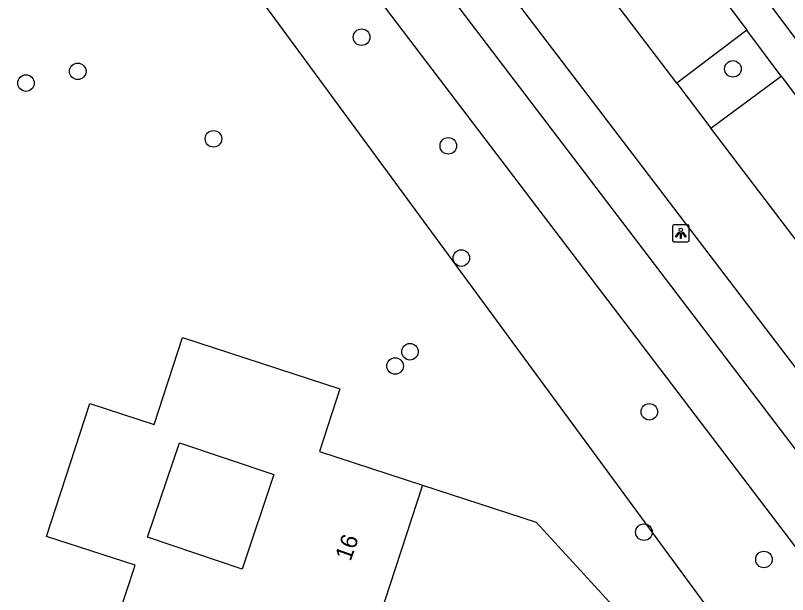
# Model space of a CAD drawing. Extents: x 156664 to 157568, y 383571 to 384421.
# Drawn here: x 156849.91 to 156895.54, y 384208.09 to 384242.31 of the extents above; entities that cross this region are included whole.
import ezdxf

# ---------------------------------------------------------------- set-up
doc = ezdxf.new("R2010")
doc.units = 0
for name, color, linetype in [('IMGEO_Boom', 7, 'Continuous'), ('IMGEO_Fietspad_gesloten', 7, 'Continuous'), ('IMGEO_Groenvoorziening', 7, 'Continuous'), ('IMGEO_Lichtpunt', 7, 'Continuous'), ('IMGEO_Pand', 7, 'Continuous'), ('IMGEO_Pand_nummerreeks', 7, 'Continuous'), ('IMGEO_Parkeervlak_open', 7, 'Continuous'), ('IMGEO_Rijbaan_lokaal_gesloten', 7, 'Continuous'), ('IMGEO_Voetpad_open', 7, 'Continuous')]:
    doc.layers.add(name, color=color, linetype=linetype)

msp = doc.modelspace()

# ---------------------------------------------------------------- linework, layer by layer
at = {"layer": 'IMGEO_Boom'}
for centre in [(156870.364, 384241.022), (156892.313, 384239.149), (156853.588, 384239.003), (156850.53, 384238.308), (156861.609, 384235.014), (156875.489, 384234.602), (156876.26, 384227.968), (156873.226, 384222.435), (156872.344, 384221.592), (156887.37, 384218.887), (156887.051, 384211.775), (156894.147, 384210.162)]:
    msp.add_circle(centre, 0.489, dxfattribs=at)
at = {"layer": 'IMGEO_Fietspad_gesloten'}
for points in [[(156849.254, 384272.327), (156925.032, 384172.754), (156949.045, 384141.371)], [(156945.927, 384151.336), (156927.81, 384174.952), (156867.867, 384253.653)]]:
    msp.add_lwpolyline(points, dxfattribs=at)
at = {"layer": 'IMGEO_Groenvoorziening'}
for points in [[(156896.18, 384200.013), (156851.427, 384260.941)], [(156873.961, 384214.559), (156880.686, 384212.359), (156887.401, 384205.04), (156887.053, 384199.698)]]:
    msp.add_lwpolyline(points, dxfattribs=at)
at = {"layer": 'IMGEO_Lichtpunt'}
for p, q in [((156888.733, 384229.84), (156888.733, 384229.033)), ((156888.733, 384229.84), (156888.733, 384229.033)), ((156889.635, 384229.935), (156888.827, 384229.935)), ((156889.635, 384229.935), (156888.827, 384229.935)), ((156889.729, 384229.033), (156889.729, 384229.84)), ((156889.729, 384229.033), (156889.729, 384229.84)), ((156888.827, 384228.939), (156889.635, 384228.939)), ((156888.827, 384228.939), (156889.635, 384228.939))]:
    msp.add_line(p, q, dxfattribs=at)
for points in [[(156889.107, 384229.504), (156889.146, 384229.476), (156888.958, 384229.214), (156888.92, 384229.241), (156889.107, 384229.504)], [(156889.319, 384229.476), (156889.357, 384229.503), (156889.544, 384229.241), (156889.505, 384229.213), (156889.319, 384229.476)], [(156889.209, 384229.456), (156889.256, 384229.456), (156889.256, 384229.134), (156889.209, 384229.134), (156889.209, 384229.456)]]:
    msp.add_lwpolyline(points, dxfattribs=at)
msp.add_circle((156889.232, 384229.638), 0.0994, dxfattribs=at)
for centre, start, end in [((156888.827, 384229.84), 90, 180), ((156888.827, 384229.84), 90, 180), ((156889.635, 384229.84), 0, 90), ((156889.635, 384229.84), 0, 90), ((156888.827, 384229.033), 180, 270), ((156888.827, 384229.033), 180, 270), ((156889.635, 384229.033), 270, 0), ((156889.635, 384229.033), 270, 360)]:
    msp.add_arc(centre, 0.0946, start, end, dxfattribs=at)
at = {"layer": 'IMGEO_Pand'}
for points in [[(156866.597, 384204.873), (156866.069, 384203.268), (156855.917, 384206.59), (156856.974, 384209.822), (156851.734, 384211.527), (156854.296, 384219.378), (156858.108, 384218.134), (156859.786, 384223.277), (156869.084, 384220.243), (156867.877, 384216.545), (156873.961, 384214.559)], [(156863.304, 384209.597), (156857.719, 384211.478), (156859.6, 384217.062), (156865.185, 384215.181), (156863.304, 384209.597)], [(156873.961, 384214.559), (156872.032, 384208.65), (156870.925, 384205.255), (156867.13, 384206.495), (156866.597, 384204.873)]]:
    msp.add_lwpolyline(points, dxfattribs=at)
at = {"layer": 'IMGEO_Parkeervlak_open'}
for points in [[(156893.129, 384241.435), (156888.996, 384238.303)], [(156891.001, 384235.643), (156895.163, 384238.727)]]:
    msp.add_lwpolyline(points, dxfattribs=at)
at = {"layer": 'IMGEO_Rijbaan_lokaal_gesloten'}
for points in [[(156869.636, 384256.091), (156947.883, 384153.474), (156948.198, 384153.058)], [(156888.996, 384238.303), (156878.44, 384252.173)], [(156888.996, 384238.303), (156891.001, 384235.643)], [(156901.645, 384221.683), (156891.001, 384235.643)]]:
    msp.add_lwpolyline(points, dxfattribs=at)
at = {"layer": 'IMGEO_Voetpad_open'}
for points in [[(156879.806, 384262.53), (156939.02, 384183.696), (156943.34, 384177.955), (156946.64, 384173.562), (156953.814, 384164.012), (156954.003, 384163.76)], [(156882.665, 384255.414), (156893.129, 384241.435)], [(156895.163, 384238.727), (156893.129, 384241.435)], [(156895.163, 384238.727), (156905.644, 384224.752)]]:
    msp.add_lwpolyline(points, dxfattribs=at)

# ---------------------------------------------------------------- texts
at = {"layer": 'IMGEO_Pand_nummerreeks'}
msp.add_text('16', height=1, rotation=70.3518, dxfattribs=at).set_placement((156869.71, 384210.018))

doc.saveas('drawing.dxf')
